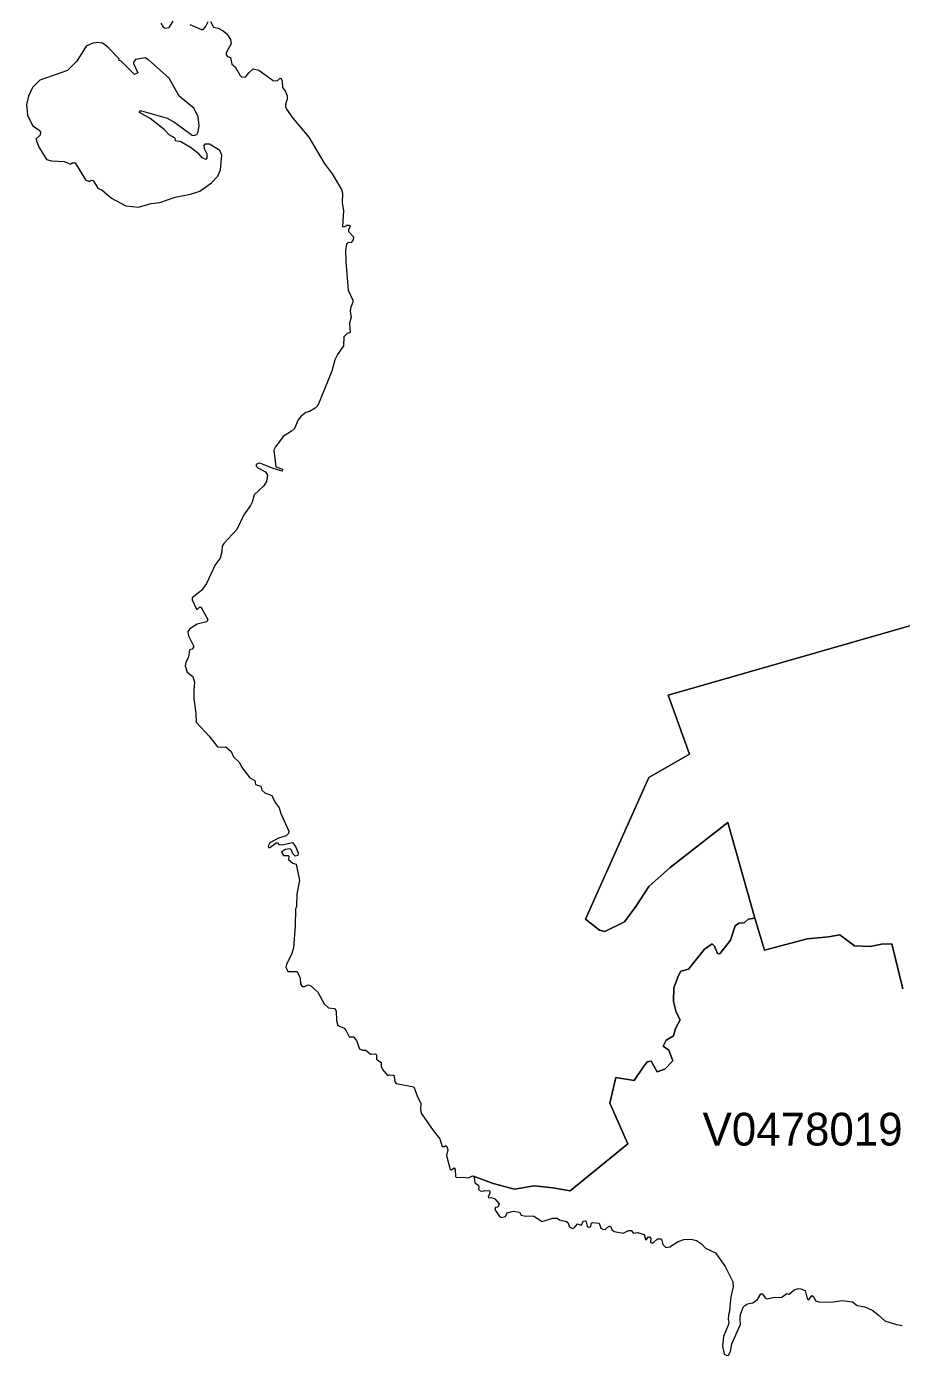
# Model space of a CAD drawing. Extents: x 369010 to 735936, y 6377141 to 6616555.
# Drawn here: x 445429 to 448095, y 6493930 to 6497979 of the extents above; entities that cross this region are included whole.
import ezdxf
from ezdxf.enums import TextEntityAlignment as Align

# ---------------------------------------------------------------- set-up
doc = ezdxf.new("R2010")
doc.units = 0
doc.header["$LTSCALE"] = 40
doc.layers.add('3', color=7, linetype='Continuous', lineweight=13)
doc.layers.add('4', color=7, linetype='Continuous')

msp = doc.modelspace()

# ---------------------------------------------------------------- linework, layer by layer
at = {"layer": '3'}
for points in [[(445837.66, 6497989.69), (445844.78, 6497977.44), (445851.56, 6497974.46), (445863.15, 6497976.78), (445875.56, 6497996.14)], [(445926.53, 6497985.72), (445961.79, 6497969.99), (445966.92, 6497969.99), (445974.36, 6497978.1), (445982.47, 6497994.49)], [(445988.93, 6497994.49), (445998.53, 6497977.77), (446012.76, 6497974.13), (446027.66, 6497966.35), (446038.91, 6497956.75), (446050.33, 6497940.2), (446051.99, 6497926.3), (446036.76, 6497899.82), (446036.76, 6497893.37), (446041.23, 6497888.57), (446050, 6497884.93), (446054.14, 6497864.57), (446064.9, 6497856.79), (446079.29, 6497829.98), (446084.26, 6497825.84), (446096.18, 6497825.18), (446105.94, 6497838.42), (446119.51, 6497851), (446136.56, 6497846.53), (446179.92, 6497814.92), (446192.17, 6497814.26), (446201.77, 6497821.7), (446204.42, 6497821.04), (446207.73, 6497813.26), (446208.55, 6497793.9), (446216.99, 6497783.14), (446223.45, 6497768.58), (446223.12, 6497756.66), (446218.65, 6497747.39), (446217.66, 6497735.97), (446220.97, 6497727.37), (446240.33, 6497700.55), (446288.99, 6497641.97), (446335.33, 6497563.19)], [(446335.33, 6497563.19), (446359.82, 6497530.58), (446388.95, 6497483.08), (446391.77, 6497471.33), (446391.1, 6497441.71), (446394.75, 6497418.37), (446391.77, 6497369.22), (446398.88, 6497370.21), (446404.34, 6497374.18), (446412.45, 6497374.51), (446415.43, 6497370.54), (446410.3, 6497360.61), (446410.3, 6497355.31), (446425.36, 6497338.27), (446424.2, 6497329.83), (446417.75, 6497320.89), (446407.99, 6497320.23), (446404.18, 6497316.58), (446400.54, 6497298.21), (446401.53, 6497263.29), (446408.65, 6497176.07), (446423.21, 6497145.62), (446422.88, 6497139.83), (446415.76, 6497120.79), (446415.1, 6497110.86), (446417.75, 6497093.32), (446413.45, 6497075.94), (446414.77, 6497046.81), (446406.33, 6497043.67), (446395.74, 6497034.24), (446394.75, 6497006.76), (446376.37, 6496979.62), (446368.26, 6496964.06), (446358.83, 6496929.14), (446316.46, 6496824.54), (446307.86, 6496816.1), (446290.64, 6496806.17), (446279.72, 6496803.19), (446264.16, 6496790.94), (446256.71, 6496780.85), (446245.46, 6496754.7), (446236.36, 6496746.26), (446211.2, 6496729.87), (446187.37, 6496698.43), (446182.07, 6496688.83), (446188.86, 6496637.69), (446208.55, 6496630.57), (446207.73, 6496624.45), (446180.58, 6496632.89), (446142.35, 6496648.11), (446136.56, 6496648.45), (446128.45, 6496644.47), (446128.78, 6496640), (446133.91, 6496634.21), (446157.25, 6496622.3), (446163.37, 6496611.87), (446160.39, 6496592.84), (446151.79, 6496579.6), (446121.99, 6496552.45), (446116.53, 6496530.44), (446111.73, 6496519.52), (446090.71, 6496491.05), (446069.36, 6496446.2), (446029.64, 6496403.83), (446024.84, 6496396.05), (446023.85, 6496378.67), (446018.55, 6496359.64), (446003.82, 6496339.12), (445976.68, 6496282.02), (445961.46, 6496260.34), (445932.99, 6496238.33), (445932.99, 6496232.53), (445946.23, 6496203.9), (445949.21, 6496203.57), (445956.32, 6496211.51), (445960.79, 6496209.36), (445980.82, 6496172.46), (445978.5, 6496165.01), (445948.88, 6496157.89), (445925.87, 6496143.99), (445919.75, 6496135.71), (445922.07, 6496122.64), (445938.45, 6496090.37), (445933.32, 6496081.76), (445924.88, 6496080.44), (445922.4, 6496057.43), (445914.62, 6496042.54), (445911.97, 6496031.61), (445918.09, 6496011.92), (445935.64, 6495999.01), (445940.93, 6495981.3), (445938.12, 6495957.3), (445938.45, 6495930.16), (445944.91, 6495885.64), (445945.9, 6495859.65), (445985.62, 6495816.46), (446010.61, 6495784.02), (446018.89, 6495782.86), (446035.77, 6495784.35), (446052.15, 6495769.95)], [(446712.35, 6494556.31), (446708.21, 6494538.77), (446719.46, 6494495.9), (446724.26, 6494495.57), (446732.04, 6494501.69), (446735.35, 6494496.23), (446736.18, 6494475.21), (446739.49, 6494471.57), (446758.85, 6494473.23), (446775.74, 6494471.24), (446787.65, 6494476.7), (446790.8, 6494475.87), (446850.54, 6494453.53), (446915.42, 6494435.99), (446975.83, 6494446.25), (447032.43, 6494440.62), (447085.39, 6494431.35), (447260.83, 6494574.35), (447206.05, 6494698.81), (447224.75, 6494776.76), (447280.36, 6494767.49), (447307.67, 6494808.37), (447320.74, 6494824.09), (447332.82, 6494826.08), (447350.37, 6494793.48), (447374.53, 6494801.92), (447398.69, 6494827.9), (447386.61, 6494859.51), (447368.9, 6494872.42), (447378.17, 6494890.13), (447400.51, 6494904.03), (447406.97, 6494926.38), (447420.87, 6494952.36), (447408.79, 6494975.53), (447400.51, 6495007.97), (447401.51, 6495049.84), (447415.41, 6495087.91), (447422.86, 6495100.82), (447446.03, 6495106.44), (447495.18, 6495167.68), (447518.35, 6495183.57), (447525.8, 6495176.95), (447535.07, 6495154.77), (447541.69, 6495153.78), (447574.13, 6495195.65), (447588.03, 6495239.18), (447600.11, 6495246.63), (447616, 6495247.62), (447627.92, 6495258.71), (447648.44, 6495262.51), (447566.51, 6495553.97), (447390.09, 6495416.43), (447325.21, 6495359), (447286.15, 6495297.6), (447250.9, 6495251.26), (447191.48, 6495221.47), (447174.77, 6495225.28), (447132.07, 6495258.71), (447325.21, 6495691.34), (447449.5, 6495762.01), (447384.62, 6495942.07), (448290.76, 6496202.08)], [(448290.76, 6496202.08), (447384.62, 6495942.07), (447449.5, 6495762.01), (447325.21, 6495691.34), (447132.07, 6495258.71), (447174.77, 6495225.28), (447191.48, 6495221.47), (447250.9, 6495251.26), (447286.15, 6495297.6), (447325.21, 6495359), (447390.09, 6495416.43), (447566.51, 6495553.97), (447648.44, 6495262.51)], [(446052.15, 6495769.95), (446058.94, 6495754.06), (446077.14, 6495737.51), (446085.58, 6495720.13), (446109.42, 6495690.34), (446124.31, 6495681.74), (446125.97, 6495669.65), (446142.68, 6495664.52), (446145.99, 6495651.95), (446154.93, 6495644.5), (446175.95, 6495635.73), (446186.71, 6495614.71), (446198.62, 6495597.99), (446204.08, 6495581.11), (446228.25, 6495527.16), (446227.09, 6495520.7), (446219.97, 6495512.76), (446196.31, 6495506.3), (446170.16, 6495491.41), (446165.03, 6495481.31), (446166.35, 6495477.5), (446170.16, 6495477.5), (446189.52, 6495491.74), (446193.16, 6495491.74), (446197.96, 6495486.44), (446208.22, 6495486.11), (446239.34, 6495492.4), (446248.11, 6495480.32), (446256.71, 6495461.62), (446255.39, 6495452.84), (446247.12, 6495451.02), (446240.66, 6495458.14), (446236.69, 6495469.39), (446232.22, 6495473.86), (446216.99, 6495471.05), (446205.74, 6495463.6), (446211.86, 6495453.51), (446226.1, 6495453.18), (446227.75, 6495451.35), (446227.09, 6495441.26), (446240.5, 6495429.67), (446249.93, 6495426.69), (446261.02, 6495377.04), (446252.25, 6495335.01), (446251.58, 6495297.77), (446248.44, 6495289.99), (446247.45, 6495238.68), (446241.82, 6495171.49), (446237.68, 6495154.61), (446220.63, 6495121.01), (446219.31, 6495112.73), (446224.77, 6495099.49), (446253.57, 6495099.49), (446262.51, 6495079.14), (446263.17, 6495062.26), (446268.96, 6495054.15), (446275.58, 6495054.15), (446286.84, 6495059.44), (446293.95, 6495057.46), (446316.79, 6495037.1), (446335.99, 6495000.85), (446348.57, 6494988.61), (446367.27, 6494986.62), (446372.4, 6494979.17), (446373.06, 6494949.88), (446377.86, 6494934.65), (446396.73, 6494926.54), (446403.19, 6494918.76), (446411.46, 6494900.72), (446425.36, 6494900.72), (446433.8, 6494889.14), (446443.57, 6494864.48), (446452.17, 6494859.68), (446462.93, 6494859.68), (446477.17, 6494847.43), (446492.39, 6494849.25), (446494.87, 6494845.78), (446495.54, 6494832.54), (446509.11, 6494822.11), (446509.11, 6494810.85), (446513.25, 6494801.26), (446528.8, 6494782.72), (446535.26, 6494785.04), (446546.51, 6494784.04), (446550.82, 6494780.24), (446549.49, 6494778.25), (446551.48, 6494763.69), (446555.28, 6494758.89), (446608.91, 6494748.13), (446619, 6494720.99), (446630.26, 6494697.82), (446629.26, 6494679.11), (446631.25, 6494667.69), (446667.83, 6494614.73), (446687.85, 6494589.91), (446695.8, 6494566.57), (446702.91, 6494566.9), (446705.23, 6494569.88), (446710.03, 6494566.9), (446712.35, 6494556.31)], [(447648.44, 6495262.51), (447627.92, 6495258.71), (447616, 6495247.62), (447600.11, 6495246.63), (447588.03, 6495239.18), (447574.13, 6495195.65), (447541.69, 6495153.78), (447535.07, 6495154.77), (447525.8, 6495176.95), (447518.35, 6495183.57), (447495.18, 6495167.68), (447446.03, 6495106.44), (447422.86, 6495100.82), (447415.41, 6495087.91), (447401.51, 6495049.84), (447400.51, 6495007.97), (447408.79, 6494975.53), (447420.87, 6494952.36), (447406.97, 6494926.38), (447400.51, 6494904.03), (447378.17, 6494890.13), (447368.9, 6494872.42), (447386.61, 6494859.51), (447398.69, 6494827.9), (447374.53, 6494801.92), (447350.37, 6494793.48), (447332.82, 6494826.08), (447320.74, 6494824.09), (447307.67, 6494808.37), (447280.36, 6494767.49), (447224.75, 6494776.76), (447206.05, 6494698.81), (447260.83, 6494574.35), (447085.39, 6494431.35), (447032.43, 6494440.62), (446975.83, 6494446.25), (446915.42, 6494435.99), (446850.54, 6494453.53), (446790.8, 6494475.87), (446793.44, 6494471.57), (446795.1, 6494455.85), (446806.35, 6494448.73), (446807.68, 6494442.61), (446805.69, 6494436.32), (446810.82, 6494430.86), (446819.26, 6494429.86), (446823.57, 6494432.51), (446840.94, 6494431.19), (446840.94, 6494423.41), (446835.48, 6494414.14), (446836.48, 6494409.51), (446846.07, 6494410.5), (446856.17, 6494407.36), (446868.75, 6494392.13), (446864.61, 6494381.54), (446857.83, 6494380.21), (446856.17, 6494374.09), (446869.41, 6494354.73), (446875.2, 6494350.42), (446888.77, 6494353.4), (446893.24, 6494363.99), (446913.27, 6494369.12), (446930.81, 6494366.64), (446935.94, 6494357.21), (446945.71, 6494354.89), (446974.67, 6494353.73), (446999.99, 6494337.51), (447031.6, 6494348.27), (447045.84, 6494347.61), (447052.95, 6494343.31), (447074.64, 6494337.51), (447078.11, 6494334.7), (447083.24, 6494321.96), (447092.34, 6494316.49), (447097.81, 6494318.48), (447107.57, 6494330.4), (447119.82, 6494326.92), (447124.95, 6494339.17), (447133.72, 6494339.83), (447137.53, 6494323.94), (447141.17, 6494320.14), (447147.95, 6494321.96), (447150.77, 6494333.04), (447153.75, 6494334.7), (447174.43, 6494332.71), (447178.9, 6494317.16), (447187.34, 6494313.35), (447193.14, 6494314.51), (447203.4, 6494323.28), (447209.36, 6494321.29), (447212.5, 6494313.35), (447219.62, 6494306.89), (447246.76, 6494302.59), (447263.31, 6494310.37), (447271.59, 6494310.04), (447279.03, 6494301.93), (447290.78, 6494303.92), (447310.81, 6494298.12), (447315.28, 6494282.57), (447317.6, 6494282.23)], [(447648.44, 6495262.51), (447678.06, 6495164.87), (447808.15, 6495199.29), (447872.53, 6495205.75), (447907.78, 6495211.21), (447952.47, 6495177.78), (447999.8, 6495175.96), (448034.06, 6495182.58), (448065.67, 6495184.4), (448099.93, 6495046.86)], [(447872.53, 6495205.75), (447808.15, 6495199.29), (447678.06, 6495164.87), (447648.44, 6495262.51)], [(448099.93, 6495046.86), (448065.67, 6495184.4), (448034.06, 6495182.58), (447999.8, 6495175.96), (447952.47, 6495177.78), (447907.78, 6495211.21), (447872.53, 6495205.75)], [(447317.6, 6494282.23), (447324.38, 6494291.01), (447327.53, 6494291.01), (447331.5, 6494285.88), (447330.17, 6494275.12), (447332.33, 6494272.97), (447338.28, 6494272.64), (447351.52, 6494284.88), (447362.12, 6494285.21), (447364.1, 6494283.56), (447367.58, 6494267.67), (447376.68, 6494258.4), (447389.59, 6494260.55), (447415.08, 6494276.77), (447432.29, 6494283.23), (447454.3, 6494283.56), (447470.36, 6494280.08), (447485.58, 6494269.99), (447498.16, 6494256.09), (447530.76, 6494241.52), (447530.76, 6494239.04), (447557.58, 6494200.81), (447581.24, 6494154.3), (447582.73, 6494138.74), (447575.45, 6494107.79), (447572.14, 6494077.84), (447570.98, 6494064.93), (447567.84, 6494053.67), (447567.51, 6494039.44), (447569.16, 6494031), (447567.34, 6494021.9), (447553.27, 6493987.14), (447549.47, 6493958.18), (447554.6, 6493933.52), (447563.04, 6493929.71), (447567.84, 6493930.87), (447573.8, 6493941.46), (447578.26, 6493964.63), (447598.79, 6494010.64), (447604.25, 6494023.88), (447604.08, 6494039.44), (447604.74, 6494054.83), (447614.18, 6494078.33), (447626.09, 6494087.11), (447641.98, 6494089.75), (447656.55, 6494100.35), (447667.14, 6494116.9), (447670.95, 6494117.89), (447681.04, 6494103.99), (447685.51, 6494102.66), (447708.85, 6494106.8), (447724.4, 6494105.81), (447730.86, 6494107.46), (447745.92, 6494118.05), (447752.71, 6494116.57), (447768.26, 6494129.47), (447780.51, 6494133.28), (447788.29, 6494132.95), (447801.53, 6494127.49), (447808.31, 6494103.32), (447813.11, 6494098.69), (447821.89, 6494111.93), (447827.02, 6494108.79), (447832.97, 6494096.21), (447843.24, 6494092.9), (447881.96, 6494091.91), (447913.08, 6494097.2), (447946.34, 6494093.23), (447960.25, 6494081.64), (447983.42, 6494077.67), (448008.08, 6494066.75), (448024.79, 6494053.51), (448044.49, 6494035.14), (448080.24, 6494023.72), (448097.95, 6494020.41)]]:
    msp.add_lwpolyline(points, dxfattribs=at)
msp.add_lwpolyline([(445646, 6497930.94), (445630.28, 6497929.28), (445610.59, 6497919.52), (445581.79, 6497874), (445552.99, 6497845.87), (445468.75, 6497815.58), (445446.74, 6497793.24), (445434.16, 6497767.42), (445428.7, 6497741.43), (445431.84, 6497709.16), (445447.07, 6497677.55), (445466.76, 6497663.98), (445471.23, 6497657.52), (445469.91, 6497648.42), (445457.99, 6497636.84), (445458.65, 6497629.72), (445466.76, 6497610.35), (445489.77, 6497574.77), (445504.5, 6497570.3), (445543.39, 6497567.99), (445563.09, 6497559.54), (445567.89, 6497564.18), (445577.32, 6497564.18), (445607.94, 6497512.71), (445619.52, 6497507.58), (445625.65, 6497511.38), (445632.1, 6497510.56), (445646, 6497486.89), (445659.25, 6497480.43), (445687.05, 6497455.94), (445731.4, 6497433.27), (445770.13, 6497429.46), (445808.86, 6497440.05), (445834.84, 6497443.03), (445882.01, 6497459.41), (445928.52, 6497468.19), (445956.99, 6497478.12), (445992.74, 6497502.78), (446012.1, 6497523.8), (446020.21, 6497542.5), (446023.85, 6497587.68), (446017.73, 6497601.58), (445985.95, 6497620.62), (445971.72, 6497621.28), (445968.9, 6497617.14), (445970.23, 6497607.71), (445977.84, 6497591.32), (445978.17, 6497578.41), (445974.7, 6497574.44), (445963.44, 6497578.91), (445953.35, 6497591.98), (445928.52, 6497611.02), (445898.4, 6497628.06), (445882.34, 6497630.71), (445881.35, 6497639.65), (445863.15, 6497649.41), (445848.42, 6497665.3), (445805.72, 6497698.9), (445772.45, 6497717.27), (445773.44, 6497723.06), (445778.9, 6497723.06), (445857.35, 6497699.89), (445881.02, 6497687.48), (445932.99, 6497648.09), (445938.78, 6497647.43), (445947.88, 6497650.41), (445952.02, 6497658.85), (445954.67, 6497678.21), (445951.69, 6497704.03), (445939.11, 6497729.52), (445894.26, 6497767.09), (445863.15, 6497822.03), (445800.59, 6497878.14), (445790.16, 6497883.6), (445761.03, 6497878.8), (445754.91, 6497871.35), (445754.91, 6497866.89), (445767.82, 6497838.09), (445757.55, 6497833.62), (445717.5, 6497873.67), (445710.05, 6497877.15), (445711.05, 6497880.79), (445676.46, 6497916.37), (445660.57, 6497928.62)], close=True, dxfattribs=at)

# ---------------------------------------------------------------- texts
at = {"layer": '4'}
msp.add_text('V0478019', height=100, dxfattribs=at).set_placement((447793.94, 6494569.2), align=Align.CENTER)

doc.saveas('drawing.dxf')
